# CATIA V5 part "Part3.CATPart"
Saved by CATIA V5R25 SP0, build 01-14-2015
Part number: Part3
Bounding box of the stored display mesh (mm): x -7.5 to 7.5, y 0 to 13, z -8.536 to 8.536
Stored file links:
  E:\1-Dersler\1-GÜZ\Tek Seç 7-Bilgisayar Destekli Mühendislik Analizi\KİNEMATİK ANALİZ\kinematik uygulama 9-03112025\Part3.CATPart
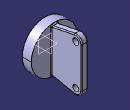
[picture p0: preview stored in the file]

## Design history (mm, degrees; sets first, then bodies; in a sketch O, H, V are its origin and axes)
Body1 (main body)
  Sketch1 on zx-plane, origin (0, 0, 0), H (-1, 0, 0), V (0, 0, 1)
    circle A1 centre (0, 0) radius 7.5
    radius A1 = 7.5
  Pad1: profile Sketch1, direction (0, 1, 0), length 3
  Sketch2 on yz-plane, origin (0, 0, 0), H (0, 1, 0), V (0, 0, 1)
    line L1 (3, 7) -> (13, 9)
    line L2 (13, 9) -> (13, -9)
    line L3 (13, -9) -> (3, -7)
    line L4 (3, -7) -> (3, 7)
    reference projected line E1 (3, 7.5) -> (3, -7.5) from edge [face of Pad1 from Sketch1.A1 | end face of Pad1]
    length L2 = 18
    length L4 = 14
    length L3 H = 10
    vertical: L2 V, L4 V
    symmetry: L1 L3 H
    coincidence: L4 E1
  Pad2: profile Sketch2, direction (1, 0, 0), length 1, mirrored extent
  Fillet1: radius 2, on edge [face of Pad2 from Sketch2.L1 | face of Pad2 from Sketch2.L2]; edge [face of Pad2 from Sketch2.L2 | face of Pad2 from Sketch2.L3]
  Sketch3 on start face of Pad2, origin (-1, 11.1986, 7.4111), H (0, 1, 0), V (0, 0, -1)
    point P1 (-0.1986, 0.8508)
    reference projected arc E1 centre (-0.1986, 0.8508) radius 2 from (-0.5908, -1.1104) to (1.8014, 0.8508) ccw from edge [start face of Pad2 | face of Fillet1]
    concentricity: E1 P1
  Hole1: placed by Sketch3, at (-1, 11, 6.5604) direction (1, 0, 0), diameter 2, depth 10, V-bottom angle 120
  Sketch4 on start face of Pad2, origin (-1, 11.8936, -7.1341), H (0, 1, 0), V (0, 0, -1)
    point P1 (-0.8936, -0.5737)
    reference projected arc E1 centre (-0.8936, -0.5737) radius 2 from (1.1064, -0.5737) to (-1.2859, 1.3875) ccw from edge [start face of Pad2 | face of Fillet1]
    concentricity: E1 P1
  Hole2: placed by Sketch4, at (-1, 11, -6.5604) direction (1, 0, 0), diameter 2, depth 10, V-bottom angle 120
  Fillet2: radius 0.3, on edge [end face of Pad1 | end face of Pad2]; edge [face of Pad2 from Sketch2.L3 | end face of Pad1]; edge [start face of Pad2 | end face of Pad1]; edge [end face of Pad1 | face of Pad2 from Sketch2.L1]; edge [start face of Pad2 | face of Pad2 from Sketch2.L1]; edge [face of Pad2 from Sketch2.L1 | end face of Pad2]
